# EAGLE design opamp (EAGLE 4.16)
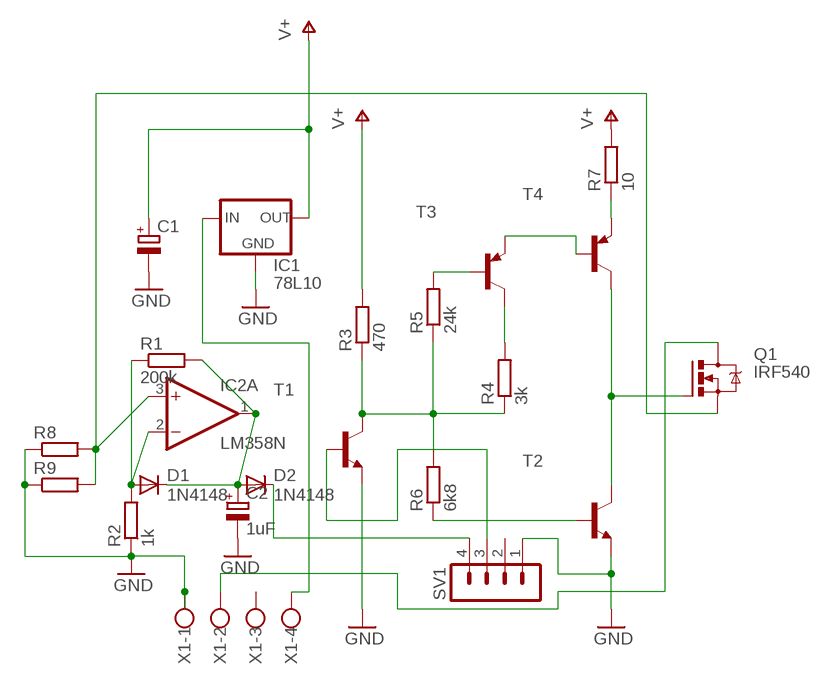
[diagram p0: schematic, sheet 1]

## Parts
C1  CPOL-EUE5-10.5  [E5-10,5]
C2  1uF  CPOL-EUE5-10.5  [E5-10,5]
D1  1N4148  [DO35-10]
D2  1N4148  [DO35-10]
IC1  78L10  78LXX  [78LXX]
IC2  LM358N  [DIL08]
Q1  IRF540  [TO220BV]
R1  200k  R-EU_0207/10  [0207/10]
R2  1k  R-EU_0207/10  [0207/10]
R3  470  R-EU_0207/10  [0207/10]
R4  3k  R-EU_0207/10  [0207/10]
R5  24k  R-EU_0207/10  [0207/10]
R6  6k8  R-EU_0207/10  [0207/10]
R7  10  R-EU_0207/10  [0207/10]
R8  R-EU_0613/15  [P0613/15]
R9  R-EU_0613/15  [P0613/15]
SV1  MA04-1  [MA04-1]
T1  BC550C-NPN-TO92-EBC  [TO92-EBC]
T2  BC550C-NPN-TO92-EBC  [TO92-EBC]
T3  BC557B-PNP-TO92-EBC  [TO92-EBC]
T4  BC557B-PNP-TO92-EBC  [TO92-EBC]
X1  W237-4  [W237-4]

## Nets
GND: C1.- C2.- IC1.GND R2.1 R8.1 R9.1 SV1.1 T1.E T2.E X1.1
N$1: D2.C SV1.4
N$2: D1.A IC2.2(A:-IN) R1.1 R2.2
N$3: R3.1 R4.1 R5.1 R6.2 T1.C
N$4: R5.2 T3.B
N$5: R4.2 T3.C
N$6: T3.E T4.B
N$7: Q1.G T2.C T4.C
N$8: R7.1 T4.E
N$9: R6.1 T2.B
N$10: IC2.3(A:+IN) Q1.S R8.2 R9.2
N$11: SV1.3 T1.B
N$12: IC1.IN X1.4
N$14: Q1.D X1.2
N$18: D1.C D2.A IC2.1(A:OUT) R1.2
V+: C1.+ IC1.OUT R3.2 R7.2
Unconnected: C2.+ IC2.5(B:+IN) IC2.6(B:-IN) IC2.7(B:OUT) SV1.2 X1.3

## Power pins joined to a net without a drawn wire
V+: IC2.8(P:V+)
V-: IC2.4(P:V-)

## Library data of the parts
C1 C2 = rcl:CPOL-EU: POLARIZED CAPACITOR, European symbol
D1 D2 = diode:1N4148: DIODE
IC1 = v-reg:78LXX: VOLTAGE REGULATOR
IC2 = linear:LM358: OP AMP also LM158; LM258; LM2904 Source: http://cache.national.com/ds/LM/LM158.pdf
Q1 = transistor-power:IRF540: HEXFET Power MOSFET
R1-R9 = rcl:R-EU_: RESISTOR, European symbol
SV1 = con-lstb:MA04-1: PIN HEADER
T1 T2 = transistor:*-NPN-: NPN Transistror
T3 T4 = transistor:*-PNP-: PNP Transistror
X1 = con-wago-500:W237-4: WAGO SCREW CLAMP

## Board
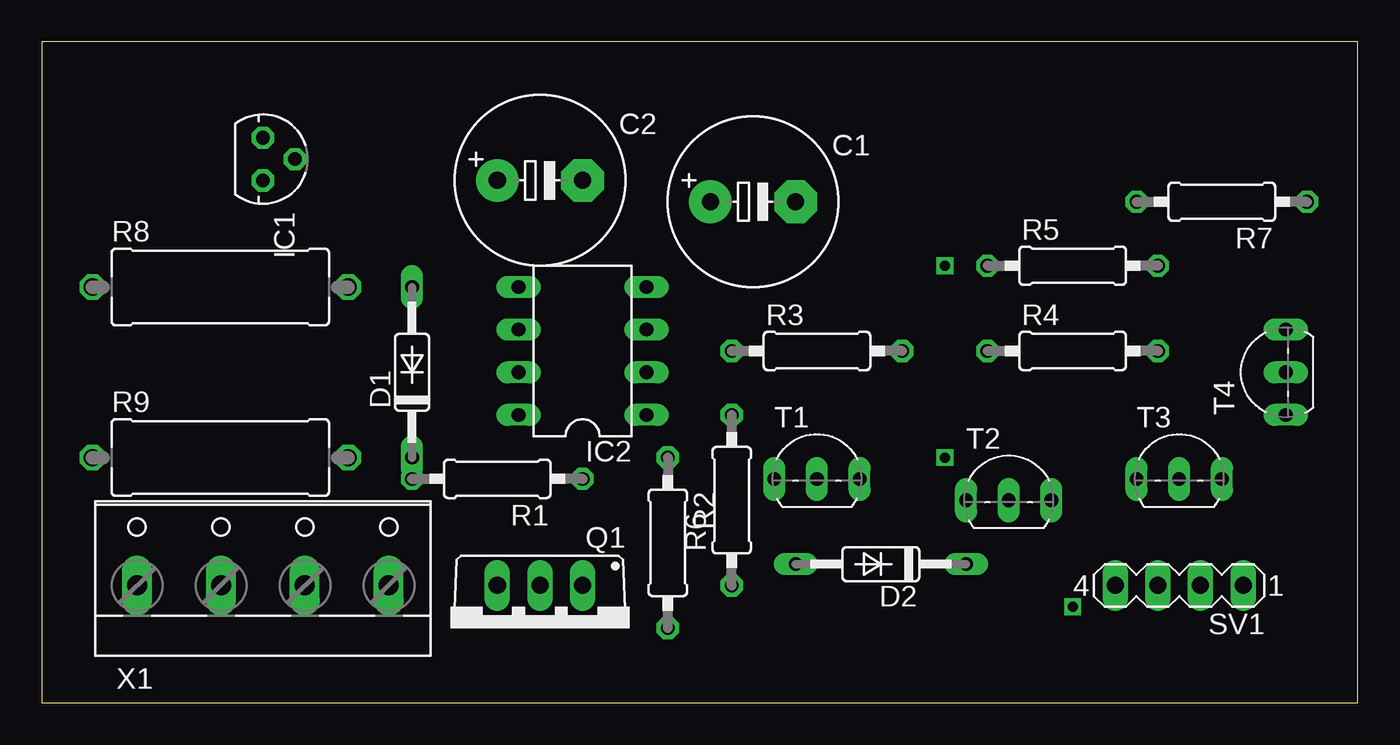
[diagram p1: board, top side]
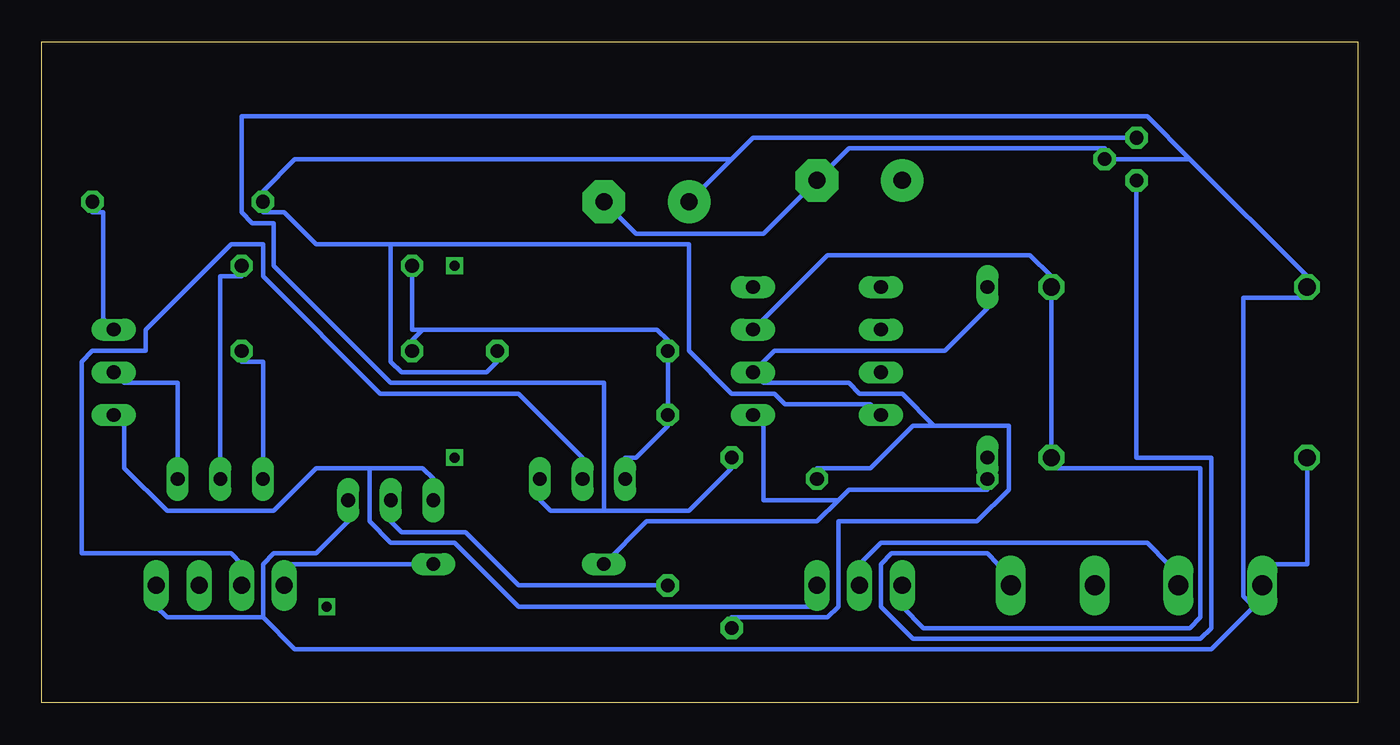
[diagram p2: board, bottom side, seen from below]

Size 78.41 x 39.36 mm. Coordinates in mm from the lower left corner, seen from the top.
Outline: 0,0 78.41,0 78.41,39.36 0,39.36 0,0
Copper layers (1*16): Top 0.035mm / dielectric 1.5mm / Bottom 0.035mm
Design rules "default": minimum track width 10mil, minimum drill 24mil, track to track 8mil, track to pad 8mil, pad to pad 8mil, via to via 8mil, smd to smd 8mil, copper to edge 40mil, drill to drill 8mil, minimum pad ring 10mil, minimum via ring 8mil, stop-mask expansion 4mil, vias tented up to drill 0mil, thermal gap 10mil
tRestrict: area 22.1,3.2 to 46.2,36.2; area 3,1.9 to 23.3,18.4; area 1.7,22.2 to 19.5,28.6; area 19.5,17.1 to 24.6,28.6; area 10.6,28.6 to 17,36.2; area 55.1,18.4 to 67.8,27.3; area 53.8,9.5 to 62.7,14.6; area 64,27.3 to 76.7,32.4; area 61.4,3.2 to 75.4,9.5; area 43.6,5.7 to 57.6,10.8; area 64,10.8 to 71.6,15.9; area 37.3,24.8 to 48.7,34.9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

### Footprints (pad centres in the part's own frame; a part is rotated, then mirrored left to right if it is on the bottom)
E5-10,5 = drill 1.016 pad 2.54 round: + -2.54,0 | drill 1.016 pad 2.54 octagon: - 2.54,0
DO35-10 = drill 0.813 long: A 5.08,0; C -5.08,0
78LXX = drill 0.813 octagon: GND 0,1.905; IN 1.27,0; OUT -1.27,0
DIL08 = drill 0.813 long: 1 -3.81,-3.81; 2 -1.27,-3.81; 3 1.27,-3.81; 4 3.81,-3.81; 5 3.81,3.81; 6 1.27,3.81; 7 -1.27,3.81; 8 -3.81,3.81
TO220BV = drill 1.016 long: D 0,-2.54; G -2.54,-2.54; S 2.54,-2.54
0207/10 = drill 0.813 octagon: 1 -5.08,0; 2 5.08,0
P0613/15 = drill 1.016 octagon: 1 -7.62,0; 2 7.62,0
MA04-1 = drill 1.016 long: 1 -3.81,0; 2 -1.27,0; 3 1.27,0; 4 3.81,0
TO92-EBC = drill 0.813 long: B 0,-1.27; C -2.54,-1.27; E 2.54,-1.27
W237-4 = drill 1.194 long: 1 -7.5,-1.27; 2 -2.5,-1.27; 3 2.5,-1.27; 4 7.5,-1.27

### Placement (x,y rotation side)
C1  42.38,29.84 0 top
C2  29.68,31.11 0 top
D1  22.06,19.68 90 top
D2  50,8.25 180 top
IC1  13.17,32.38 270 top
IC2  32.22,20.95 90 top
Q1  29.68,4.44 180 top
R1  27.14,13.33 180 top
R2  37.3,9.52 270 top
R3  46.19,20.95 0 top
R4  61.43,20.95 0 top
R5  61.43,26.03 0 top
R6  41.11,12.06 90 top
R7  70.32,29.84 180 top
R8  10.63,24.76 0 top
R9  10.63,14.6 0 top
SV1  67.78,6.98 180 top
T1  46.19,14.6 0 top
T2  57.62,13.33 0 top
T3  67.78,14.6 0 top
T4  72.86,19.68 90 top
X1  13.17,8.25 0 top

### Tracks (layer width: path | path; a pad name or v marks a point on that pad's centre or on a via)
GND
  Bottom 0.254: R9.1 3.01,8.25 4.92,8.25 X1.1 6.18,5.71 | 65.24,5.08 65.24,8.25 64.61,8.89 62.06,8.89 60.16,10.79 T2.E | 65.24,5.08 70.95,5.08 71.59,5.71 SV1.1 | 6.18,5.71 8.73,3.17 63.34,3.17 65.24,5.08 | 44.92,11.43 48.09,11.43 48.73,12.06 T1.E | 44.92,11.43 39.84,11.43 37.3,13.97 R2.1 | 10,32.38 3.01,25.39 R8.1 3.01,24.12 6.82,24.12 6.82,6.34 6.18,5.71 | 10,32.38 IC1.GND 15.08,33.02 30.31,33.02 C2.- 35.39,27.93 43.02,27.93 C1.- | 44.92,11.43 44.92,19.04 57.62,19.04 64.61,26.03 64.61,28.57 65.88,28.57 66.51,29.2 66.51,34.92 12.54,34.92 10,32.38
N$1
  Bottom 0.254: D2.C 63.97,8.25 SV1.4
N$2
  Bottom 0.254: 25.23,16.5 26.5,16.5 29.04,13.97 32.22,13.97 R1.1 | 25.23,16.5 20.79,16.5 20.79,12.7 22.7,10.79 30.95,10.79 30.95,5.71 31.58,5.08 37.3,5.08 R2.2 | 25.23,16.5 27.14,18.41 29.68,18.41 30.31,19.04 35.39,19.04 IC2.2 34.76,20.95 24.6,20.95 22.06,23.49 D1.A
N$3
  Bottom 0.254: T1.C 43.65,14.6 43.02,14.6 41.11,16.5 R6.2 R3.1 41.11,21.58 41.74,22.22 55.71,22.22 | 55.71,22.22 56.35,21.58 R4.1 | 55.71,22.22 56.35,22.22 R5.1
N$4
  Bottom 0.254: T3.B 67.78,25.39 66.51,25.39 R5.2
N$5
  Bottom 0.254: T3.C 65.24,20.31 66.51,20.31 R4.2
N$6
  Bottom 0.254: T3.E 70.32,19.04 73.5,19.04 T4.B
N$7
  Bottom 0.254: 58.89,13.97 62.06,13.97 64.61,11.43 70.95,11.43 73.5,13.97 73.5,16.5 T4.C | 58.89,13.97 55.71,13.97 55.08,13.33 T2.C | 58.89,13.97 58.89,10.79 57.62,9.52 53.81,9.52 50,5.71 32.22,5.71 Q1.G
N$8
  Bottom 0.254: T4.E 74.77,22.86 74.77,29.2 75.4,29.2 R7.1
N$9
  Bottom 0.254: R6.1 50,6.98 53.17,10.16 56.98,10.16 57.62,10.79 T2.B
N$10
  Bottom 0.254: IC2.3 31.58,26.66 19.52,26.66 18.25,25.39 R8.2 R9.2 18.25,13.97 9.36,13.97 9.36,5.08 10,4.44 25.87,4.44 27.14,5.71 Q1.S
N$11
  Bottom 0.254: T1.B 46.19,14.6 50,18.41 58.25,18.41 65.24,25.39 65.24,27.3 67.14,27.3 72.22,22.22 72.22,20.95 75.4,20.95 76.03,20.31 76.03,8.89 67.14,8.89 66.51,8.25 SV1.3
N$12
  Bottom 0.254: IC1.IN 13.17,14.6 8.73,14.6 8.73,4.44 9.36,3.8 26.5,3.8 28.41,5.71 28.41,8.25 27.77,8.89 22.06,8.89 21.42,8.25 X1.4
N$14
  Bottom 0.254: Q1.D 29.68,8.25 28.41,9.52 12.54,9.52 11.27,8.25 X1.2
N$15  (via drill 0.6)
  other vias: 53.81,14.6
N$16  (via drill 0.6)
  other vias: 53.81,26.03
N$18
  Bottom 0.254: D1.C R1.2 22.06,12.7 30.31,12.7 30.95,12.06 | 30.95,12.06 32.22,10.79 42.38,10.79 D2.A | 30.95,12.06 35.39,12.06 35.39,16.5 IC2.1
N$21  (via drill 0.6)
  other vias: 61.43,5.71
V+
  Bottom 0.254: 37.3,32.38 36.03,33.65 IC1.OUT | 37.3,32.38 C1.+ | 57.62,27.3 62.06,27.3 63.97,29.2 65.24,29.2 R7.2 65.24,30.47 63.34,32.38 37.3,32.38 | 57.62,27.3 39.84,27.3 39.84,20.95 37.3,18.41 34.76,18.41 34.12,17.77 29.04,17.77 IC2.8 | 57.62,27.3 57.62,20.31 56.98,19.68 51.91,19.68 51.27,20.31 R3.2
